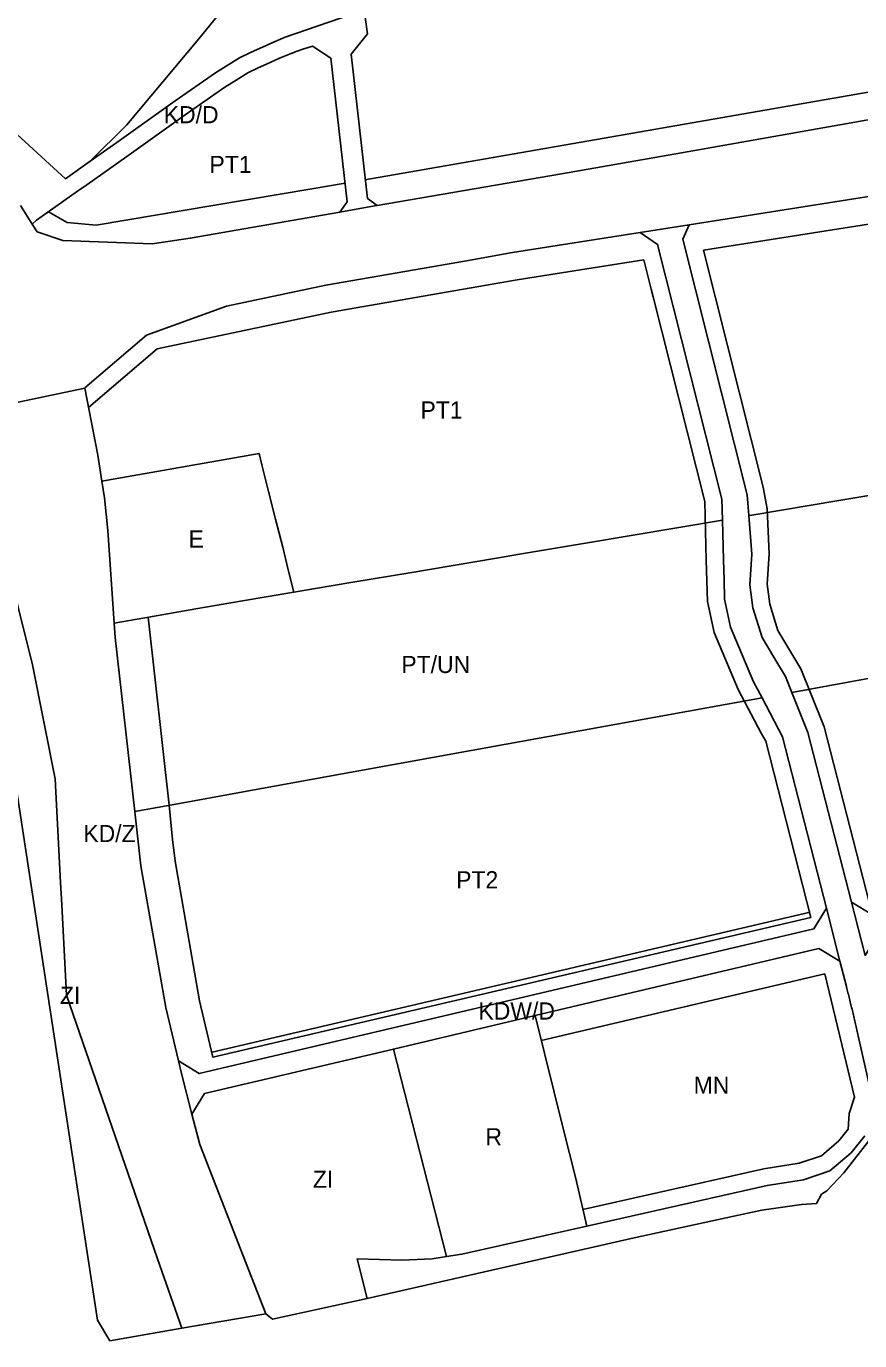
# Model space of a CAD drawing. Extents: x 7436680 to 7439366, y 5548361 to 5550775.
# Drawn here: x 7437475 to 7437960, y 5548361 to 5549127 of the extents above; entities that cross this region are included whole.
import ezdxf

# ---------------------------------------------------------------- set-up
doc = ezdxf.new("R2010")
doc.units = 0
for name, color, linetype in [('linie_rozgraniczajace', 7, 'Continuous'), ('linie_zabudowy_azurowe', 7, 'Continuous'), ('linie_zabudowy_nieprzekraczalne', 7, 'Continuous'), ('oznaczenia_przeznaczen', 7, 'Continuous')]:
    doc.layers.add(name, color=color, linetype=linetype)

msp = doc.modelspace()

# ---------------------------------------------------------------- linework, layer by layer
at = {"layer": 'linie_rozgraniczajace'}
for points in [[(7437982.05, 5549183.92), (7437999.18, 5549078.49), (7437856.52, 5549053.27), (7437786.66, 5549040.99), (7437679.21, 5549022.5), (7437673.72, 5549026.62), (7437664.11, 5549110.67), (7437673.64, 5549122.45), (7437672.21, 5549132.35)], [(7437471.46, 5549022.59), (7437478.39, 5549011.74), (7437481.28, 5549007.22), (7437496.12, 5549002.15), (7437548.26, 5549000.19), (7437570.44, 5549003.41), (7437657.52, 5549018.7), (7437677.73, 5549022.24), (7437679.21, 5549022.5), (7437786.66, 5549040.99), (7437856.52, 5549053.27), (7437999.18, 5549078.49), (7438038.34, 5549085.45), (7438100.24, 5549096.55), (7438167.47, 5549108.23), (7438255.31, 5549123.14), (7438335.28, 5549136.91), (7438356.27, 5549140.95), (7438358.93, 5549141.46), (7438420.86, 5549152.06), (7438591.21, 5549182.25)], [(7437596.84, 5549146.06), (7437575.32, 5549119.55), (7437554.36, 5549094.53), (7437533.4, 5549069.51), (7437512.2, 5549048.31), (7437497.84, 5549038.14), (7437448.25, 5549083.28)], [(7437669.71, 5549135.8), (7437625.68, 5549120.51), (7437618.48, 5549117.47), (7437610.75, 5549114.01), (7437605.8, 5549111.81), (7437599.1, 5549108.54), (7437585.07, 5549099.83), (7437561.62, 5549083.56), (7437527.68, 5549059.28), (7437512.2, 5549048.31), (7437533.4, 5549069.51), (7437554.36, 5549094.53), (7437575.32, 5549119.55), (7437596.84, 5549146.06)], [(7437448.25, 5549083.28), (7437497.84, 5549038.14), (7437512.2, 5549048.31), (7437527.68, 5549059.28), (7437561.62, 5549083.56), (7437585.07, 5549099.83), (7437599.1, 5549108.54), (7437605.8, 5549111.81), (7437610.75, 5549114.01), (7437618.48, 5549117.47), (7437625.68, 5549120.51), (7437669.71, 5549135.8)], [(7437672.21, 5549132.35), (7437673.64, 5549122.45), (7437664.11, 5549110.67), (7437673.72, 5549026.62), (7437679.21, 5549022.5), (7437677.73, 5549022.24), (7437657.52, 5549018.7), (7437661.86, 5549024.67), (7437652.3, 5549108.31), (7437641.62, 5549115.27), (7437636.03, 5549113.52), (7437632.65, 5549112.35), (7437629.27, 5549111.17), (7437622.47, 5549108.3), (7437614.83, 5549104.88), (7437610.03, 5549102.74), (7437603.94, 5549099.78), (7437597.25, 5549095.62), (7437590.56, 5549091.47), (7437567.38, 5549075.39), (7437533.48, 5549051.13), (7437510.22, 5549034.66), (7437504.68, 5549030.84), (7437480.91, 5549013.99), (7437478.39, 5549011.74), (7437471.46, 5549022.59)], [(7438435.66, 5549107.09), (7438426.37, 5549095.2), (7438388.15, 5549089.37), (7438382.5, 5549094.11), (7438287.23, 5549076.66), (7438221.26, 5549069.25), (7438143.81, 5549057.42), (7438039.46, 5549039.63), (7438027.04, 5549037.51), (7437861.01, 5549011.31), (7437832.52, 5549006.81), (7437758.08, 5548995.07), (7437731.3, 5548990.27), (7437649.47, 5548976.03), (7437591.52, 5548963.81), (7437544.99, 5548946.89), (7437509.03, 5548916.21), (7437509.07, 5548916.02), (7437435.77, 5548900.76)], [(7437966.76, 5548853.84), (7437948.11, 5548850.7), (7437897.59, 5548842.17), (7437895.78, 5548841.87), (7437894.83, 5548853.92), (7437857.3, 5549002.94), (7437861.01, 5549011.31), (7438027.04, 5549037.51)], [(7437967.57, 5548502.61), (7437959.48, 5548538.68), (7437959.29, 5548539.55), (7437959.09, 5548540.42), (7437958.89, 5548541.29), (7437958.69, 5548542.16), (7437958.5, 5548543.03), (7437958.3, 5548543.9), (7437958.1, 5548544.76), (7437957.9, 5548545.63), (7437957.7, 5548546.5), (7437957.49, 5548547.37), (7437957.29, 5548548.24), (7437957.09, 5548549.1), (7437956.88, 5548549.97), (7437956.68, 5548550.84), (7437956.47, 5548551.7), (7437956.26, 5548552.57), (7437956.06, 5548553.44), (7437955.85, 5548554.3), (7437955.64, 5548555.17), (7437955.43, 5548556.04), (7437955.22, 5548556.9), (7437955.01, 5548557.77), (7437954.79, 5548558.63), (7437954.58, 5548559.5), (7437954.37, 5548560.36), (7437954.15, 5548561.23), (7437953.94, 5548562.09), (7437953.72, 5548562.96), (7437953.5, 5548563.82), (7437953.28, 5548564.68), (7437953.07, 5548565.55), (7437952.85, 5548566.41), (7437952.63, 5548567.27), (7437952.56, 5548567.51), (7437948.82, 5548582.15), (7437940.89, 5548613.15), (7437915.39, 5548712.87), (7437903.43, 5548735.58), (7437898.42, 5548745.09), (7437885.14, 5548776.82), (7437881.63, 5548793.08), (7437881.31, 5548804.62), (7437880.98, 5548816.15), (7437880.34, 5548839.27), (7437880.01, 5548851.35), (7437842.61, 5548999.84), (7437832.52, 5549006.81), (7437861.01, 5549011.31), (7437857.3, 5549002.94), (7437894.83, 5548853.92), (7437895.78, 5548841.87), (7437897.54, 5548819.41), (7437896.41, 5548801.57), (7437898.16, 5548788.13), (7437903.42, 5548770.8), (7437910.24, 5548759.44), (7437917.05, 5548748.08), (7437920.81, 5548738.78), (7437930.18, 5548715.57), (7437955.49, 5548616.6), (7437963.42, 5548585.6)], [(7437435.77, 5548900.76), (7437509.07, 5548916.02), (7437516.63, 5548877.06), (7437518.93, 5548861.88), (7437520.41, 5548852.16), (7437522.32, 5548833.09), (7437526.03, 5548779.17), (7437526.61, 5548770.76), (7437538.19, 5548669.39), (7437538.41, 5548667.46), (7437541.73, 5548637.71), (7437556.26, 5548555.17), (7437563.58, 5548524.15), (7437565.29, 5548516.89), (7437571.4, 5548493.13), (7437575.97, 5548475.38), (7437601.31, 5548410.53), (7437614.46, 5548376.86), (7437565.56, 5548368.43), (7437551.39, 5548408.78), (7437498.43, 5548562.35), (7437495.55, 5548615.12), (7437494.85, 5548628.1), (7437491.73, 5548688.53), (7437478.52, 5548754.82), (7437462.25, 5548820.58)], [(7438406.56, 5548827.93), (7437920.81, 5548738.78), (7437917.05, 5548748.08), (7437910.24, 5548759.44), (7437903.42, 5548770.8), (7437898.16, 5548788.13), (7437896.41, 5548801.57), (7437897.54, 5548819.41), (7437895.78, 5548841.87), (7437897.59, 5548842.17), (7437948.11, 5548850.7), (7437966.76, 5548853.84)], [(7437963.3, 5548480.5), (7437955.39, 5548470.58), (7437942.97, 5548460.01), (7437927.49, 5548454.9), (7437906.4, 5548451.51), (7437801.43, 5548427.9), (7437794.7, 5548456.49), (7437787.63, 5548484.83), (7437771.24, 5548550.54), (7437936.61, 5548589.54), (7437948.82, 5548582.15), (7437952.56, 5548567.51), (7437952.63, 5548567.27), (7437952.85, 5548566.41), (7437953.07, 5548565.55), (7437953.28, 5548564.68), (7437953.5, 5548563.82), (7437953.72, 5548562.96), (7437953.94, 5548562.09), (7437954.15, 5548561.23), (7437954.37, 5548560.36), (7437954.58, 5548559.5), (7437954.79, 5548558.63), (7437955.01, 5548557.77), (7437955.22, 5548556.9), (7437955.43, 5548556.04), (7437955.64, 5548555.17), (7437955.85, 5548554.3), (7437956.06, 5548553.44), (7437956.26, 5548552.57), (7437956.47, 5548551.7), (7437956.68, 5548550.84), (7437956.88, 5548549.97), (7437957.09, 5548549.1), (7437957.29, 5548548.24), (7437957.49, 5548547.37), (7437957.7, 5548546.5), (7437957.9, 5548545.63), (7437958.1, 5548544.76), (7437958.3, 5548543.9), (7437958.5, 5548543.03), (7437958.69, 5548542.16), (7437958.89, 5548541.29), (7437959.09, 5548540.42), (7437959.29, 5548539.55), (7437959.48, 5548538.68), (7437967.57, 5548502.61)], [(7437971.92, 5548485.54), (7437950.99, 5548458.92), (7437941.1, 5548448.51), (7437937.98, 5548446.48), (7437935.1, 5548440.96), (7437926.51, 5548440.51), (7437903.38, 5548437.17), (7437886.97, 5548433.6), (7437828.99, 5548420.98), (7437673.41, 5548385.8), (7437667.61, 5548408.78)], [(7437667.61, 5548408.78), (7437693.61, 5548408.1), (7437711.23, 5548408.72), (7437719.69, 5548410.08), (7437728.64, 5548411.52), (7437801.43, 5548427.9), (7437906.4, 5548451.51), (7437927.49, 5548454.9), (7437942.97, 5548460.01), (7437955.39, 5548470.58), (7437963.3, 5548480.5)]]:
    msp.add_lwpolyline(points, dxfattribs=at)
for points in [[(7437478.39, 5549011.74), (7437480.91, 5549013.99), (7437504.68, 5549030.84), (7437510.22, 5549034.66), (7437533.48, 5549051.13), (7437567.38, 5549075.39), (7437590.56, 5549091.47), (7437597.25, 5549095.62), (7437603.94, 5549099.78), (7437610.03, 5549102.74), (7437614.83, 5549104.88), (7437622.47, 5549108.3), (7437629.27, 5549111.17), (7437632.65, 5549112.35), (7437636.03, 5549113.52), (7437641.62, 5549115.27), (7437652.3, 5549108.31), (7437661.86, 5549024.67), (7437657.52, 5549018.7), (7437570.44, 5549003.41), (7437548.26, 5549000.19), (7437496.12, 5549002.15), (7437481.28, 5549007.22)], [(7437509.03, 5548916.21), (7437544.99, 5548946.89), (7437591.52, 5548963.81), (7437649.47, 5548976.03), (7437731.3, 5548990.27), (7437758.08, 5548995.07), (7437832.52, 5549006.81), (7437842.61, 5548999.84), (7437880.01, 5548851.35), (7437880.34, 5548839.27), (7437800.58, 5548825.81), (7437763.3, 5548819.53), (7437748.81, 5548817.09), (7437698.36, 5548808.59), (7437665.07, 5548802.97), (7437630.66, 5548797.17), (7437627.46, 5548810.31), (7437624.26, 5548823.44), (7437620.15, 5548839.69), (7437616.04, 5548855.93), (7437612.16, 5548871.44), (7437610.5, 5548878.06), (7437518.93, 5548861.88), (7437516.63, 5548877.06), (7437509.07, 5548916.02)], [(7437518.93, 5548861.88), (7437610.5, 5548878.06), (7437612.16, 5548871.44), (7437616.04, 5548855.93), (7437620.15, 5548839.69), (7437624.26, 5548823.44), (7437627.46, 5548810.31), (7437630.66, 5548797.17), (7437600.87, 5548792.15), (7437573.68, 5548787.57), (7437548.38, 5548783.13), (7437526.03, 5548779.17), (7437522.32, 5548833.09), (7437520.41, 5548852.16)], [(7437440.17, 5548872), (7437462.25, 5548820.58), (7437478.52, 5548754.82), (7437491.73, 5548688.53), (7437494.85, 5548628.1), (7437495.55, 5548615.12), (7437498.43, 5548562.35), (7437551.39, 5548408.78), (7437565.56, 5548368.43), (7437523.58, 5548361.11), (7437516.41, 5548373.14)], [(7437526.03, 5548779.17), (7437548.38, 5548783.13), (7437573.68, 5548787.57), (7437600.87, 5548792.15), (7437630.66, 5548797.17), (7437665.07, 5548802.97), (7437698.36, 5548808.59), (7437748.81, 5548817.09), (7437763.3, 5548819.53), (7437800.58, 5548825.81), (7437880.34, 5548839.27), (7437880.98, 5548816.15), (7437881.31, 5548804.62), (7437881.63, 5548793.08), (7437885.14, 5548776.82), (7437898.42, 5548745.09), (7437903.43, 5548735.58), (7437648.15, 5548689.52), (7437598.14, 5548680.4), (7437564.16, 5548674.16), (7437538.19, 5548669.39), (7437526.61, 5548770.76)], [(7437920.81, 5548738.78), (7438406.56, 5548827.93), (7438408.3, 5548811.89), (7438409.18, 5548803.76), (7438412.31, 5548775.06), (7438420.83, 5548710.69), (7438412.33, 5548698.87), (7438069.39, 5548632.36), (7438029.98, 5548623.9), (7437967.7, 5548609.21), (7437955.49, 5548616.6), (7437930.18, 5548715.57)], [(7437538.19, 5548669.39), (7437564.16, 5548674.16), (7437598.14, 5548680.4), (7437648.15, 5548689.52), (7437903.43, 5548735.58), (7437915.39, 5548712.87), (7437940.89, 5548613.15), (7437933.64, 5548601.17), (7437575.61, 5548516.72), (7437563.58, 5548524.15), (7437556.26, 5548555.17), (7437541.73, 5548637.71), (7437538.41, 5548667.46)], [(7437955.49, 5548616.6), (7437967.7, 5548609.21), (7438029.98, 5548623.9), (7438069.39, 5548632.36), (7438412.33, 5548698.87), (7438420.83, 5548710.69), (7438421.18, 5548708.05), (7438424.26, 5548682.9), (7438424.86, 5548678.91), (7438413.54, 5548686.89), (7438071.68, 5548620.58), (7438032.74, 5548612.22), (7437970.68, 5548597.58), (7437963.42, 5548585.6)], [(7437563.58, 5548524.15), (7437575.61, 5548516.72), (7437933.64, 5548601.17), (7437940.89, 5548613.15), (7437948.82, 5548582.15), (7437936.61, 5548589.54), (7437771.24, 5548550.54), (7437688.72, 5548531.07), (7437578.65, 5548505.11), (7437571.4, 5548493.13), (7437565.29, 5548516.89)], [(7437688.72, 5548531.07), (7437771.24, 5548550.54), (7437787.63, 5548484.83), (7437794.7, 5548456.49), (7437801.43, 5548427.9), (7437728.64, 5548411.52), (7437719.69, 5548410.08)], [(7437571.4, 5548493.13), (7437578.65, 5548505.11), (7437688.72, 5548531.07), (7437719.69, 5548410.08), (7437711.23, 5548408.72), (7437693.61, 5548408.1), (7437667.61, 5548408.78), (7437673.41, 5548385.8), (7437653.8, 5548381.36), (7437618.35, 5548373.63), (7437614.46, 5548376.86), (7437601.31, 5548410.53), (7437575.97, 5548475.38)]]:
    msp.add_lwpolyline(points, close=True, dxfattribs=at)
at = {"layer": 'linie_zabudowy_azurowe'}
msp.add_lwpolyline([(7437583.25, 5548529.29), (7437931.49, 5548610.8)], dxfattribs=at)
at = {"layer": 'linie_zabudowy_nieprzekraczalne'}
for points in [[(7437672.18, 5549037.52), (7438316.41, 5549149.98)], [(7437515.57, 5549011.07), (7437583.48, 5549022.52), (7437641.27, 5549032.24), (7437660.62, 5549035.55)], [(7437487.91, 5549018.79), (7437498.82, 5549012.71), (7437515.57, 5549011.07)], [(7438029.53, 5549021.7), (7437869.25, 5548996.41)], [(7437869.25, 5548996.41), (7437904, 5548858.46)], [(7437834.54, 5548990.94), (7437760.74, 5548979.29)], [(7437838.89, 5548973.69), (7437834.54, 5548990.94)], [(7437760.74, 5548979.29), (7437734.08, 5548974.52), (7437652.5, 5548960.32), (7437551.05, 5548938.92)], [(7437545.96, 5548782.7), (7437558.16, 5548673.05), (7437560.14, 5548653.08), (7437561.54, 5548640.56), (7437575.86, 5548559.21), (7437583.63, 5548526.24), (7437931.94, 5548607.78), (7437905.7, 5548710.39), (7437902.88, 5548715.16), (7437889.57, 5548740.44), (7437875.56, 5548773.8), (7437871.66, 5548791.88), (7437870.99, 5548815.87), (7437870.05, 5548849.97), (7437839.99, 5548969.29), (7437838.89, 5548973.69)], [(7437551.05, 5548938.92), (7437511.15, 5548904.88)], [(7437515.22, 5548908.35), (7437551.05, 5548938.92)], [(7437904, 5548858.46), (7437906.33, 5548845.78)], [(7437906.33, 5548845.78), (7437907.56, 5548819.49)], [(7437907.56, 5548819.49), (7437906.45, 5548801.9)], [(7437906.45, 5548801.9), (7437907.97, 5548790.24)], [(7437907.97, 5548790.24), (7437912.63, 5548774.88)], [(7437912.63, 5548774.88), (7437926.03, 5548752.55)], [(7437926.03, 5548752.55), (7437938.49, 5548721.7)], [(7437938.49, 5548721.7), (7437939.7, 5548718.69)], [(7437939.7, 5548718.69), (7437966, 5548615.86)], [(7437940.04, 5548574.94), (7437774.87, 5548535.98)], [(7437957.22, 5548503.04), (7437940.04, 5548574.94)], [(7437954.25, 5548493.52), (7437957.22, 5548503.04)], [(7437953.56, 5548484.33), (7437954.25, 5548493.52)], [(7437948.17, 5548477.57), (7437953.56, 5548484.33)], [(7437937.98, 5548468.9), (7437948.17, 5548477.57)], [(7437904.51, 5548461.34), (7437925.11, 5548464.65)], [(7437925.11, 5548464.65), (7437937.98, 5548468.9)], [(7437799.14, 5548437.63), (7437904.51, 5548461.34)]]:
    msp.add_lwpolyline(points, dxfattribs=at)

# ---------------------------------------------------------------- texts
at = {"layer": 'oznaczenia_przeznaczen'}
for s, p in [('KD/D', (7437554.99, 5549070.44)), ('PT1', (7437581.6, 5549041.46)), ('PT1', (7437704.51, 5548898.38)), ('E', (7437569.46, 5548823.24)), ('PT/UN', (7437693.36, 5548750.12)), ('KD/Z', (7437508.13, 5548651.63)), ('PT2', (7437725.28, 5548624.66)), ('ZI', (7437494.53, 5548557.36)), ('KDW/D', (7437738.27, 5548548.22)), ('MN', (7437863.61, 5548505.02)), ('R', (7437742.33, 5548474.94)), ('ZI', (7437641.83, 5548450.21))]:
    msp.add_text(s, height=10, dxfattribs=at).set_placement(p)

doc.saveas('drawing.dxf')
